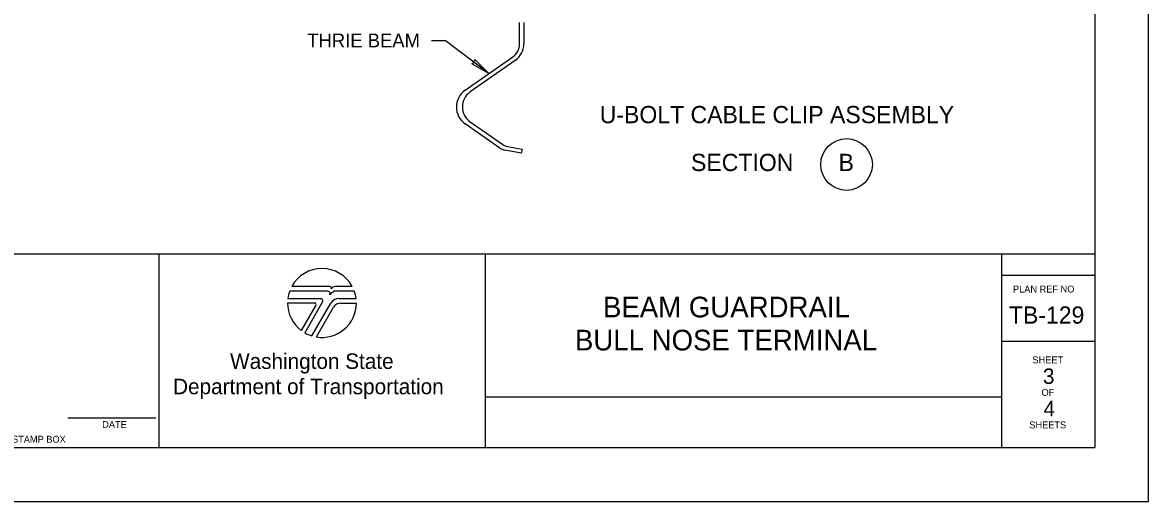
# Model space of a CAD drawing. Extents: x 1312564.2 to 1312581.5, y 1207298.4 to 1207352.6.
# Drawn here: x 1312574.93 to 1312581.48, y 1207327.22 to 1207330 of the extents above; entities that cross this region are included whole.
import ezdxf

# ---------------------------------------------------------------- set-up
doc = ezdxf.new("R2010")
doc.units = 0
for name, color, linetype in [('Level 1', 7, 'Continuous'), ('Level 15', 7, 'Continuous'), ('Level 16', 7, 'Continuous'), ('Level 2', 7, 'Continuous'), ('Level 20', 7, 'Continuous'), ('Level 36', 7, 'Continuous'), ('Level 63', 7, 'Continuous'), ('Level 9', 7, 'Continuous'), ('SH_GI_SheetTextInCells', 7, 'Continuous')]:
    doc.layers.add(name, color=color, linetype=linetype)

msp = doc.modelspace()

# ---------------------------------------------------------------- linework, layer by layer
at = {"layer": 'Level 1'}
for p, q in [((1312581.1655, 1207337.9084), (1312581.1655, 1207327.5334)), ((1312565.4155, 1207328.6593), (1312581.1655, 1207328.6593)), ((1312575.7244, 1207328.6593), (1312575.7244, 1207327.5334)), ((1312577.621, 1207328.6593), (1312577.621, 1207327.5334)), ((1312580.6233, 1207328.6593), (1312580.6233, 1207327.5334)), ((1312580.6233, 1207328.5342), (1312581.1655, 1207328.5342)), ((1312580.6233, 1207328.151), (1312581.1655, 1207328.151)), ((1312577.621, 1207327.8288), (1312580.6233, 1207327.8288)), ((1312575.1952, 1207327.7067), (1312575.7069, 1207327.7067)), ((1312565.4155, 1207327.5334), (1312581.1655, 1207327.5334))]:
    msp.add_line(p, q, dxfattribs=at)
at = {"layer": 'Level 15'}
for p in [(1312577.3093, 1207329.8977), (1312577.6434, 1207329.7054)]:
    msp.add_line(p, (1312577.3894, 1207329.8977), dxfattribs=at)
msp.add_lwpolyline([(1312577.6434, 1207329.7054), (1312577.5433, 1207329.7625), (1312577.5565, 1207329.7712), (1312577.5613, 1207329.7863)], close=True, dxfattribs=at)
at = {"layer": 'Level 16'}
for p, q in [((1312577.8208, 1207329.8782), (1312577.8208, 1207330.0018)), ((1312577.8463, 1207330.0018), (1312577.8463, 1207329.8782)), ((1312577.505, 1207329.6088), (1312577.7818, 1207329.8021)), ((1312577.796, 1207329.7817), (1312577.534, 1207329.5987)), ((1312577.7076, 1207329.2733), (1312577.5045, 1207329.4145)), ((1312577.5342, 1207329.4249), (1312577.7234, 1207329.2934)), ((1312577.752, 1207329.2816), (1312577.8357, 1207329.2669))]:
    msp.add_line(p, q, dxfattribs=at)
msp.add_lwpolyline([(1312577.8357, 1207329.2669), (1312577.8302, 1207329.244), (1312577.7355, 1207329.2617)], dxfattribs=at)
for centre, radius, start, end in [((1312577.7282, 1207329.8776), 0.0925, 305.33624, 0.39712), ((1312577.7286, 1207329.8782), 0.1177, 304.93912, 0), ((1312577.5724, 1207329.5115), 0.1184, 124.71674, 234.96964), ((1312577.5947, 1207329.5119), 0.1059, 124.93912, 235.19201), ((1312577.7645, 1207329.3526), 0.0721, 235.19199, 259.99994), ((1312577.7487, 1207329.3325), 0.0721, 235.19199, 259.41323)]:
    msp.add_arc(centre, radius, start, end, dxfattribs=at)
at = {"layer": 'Level 2'}
msp.add_lwpolyline([(1312564.478, 1207327.2209), (1312581.478, 1207327.2209), (1312581.478, 1207338.2209), (1312564.478, 1207338.2209)], close=True, dxfattribs=at)
at = {"layer": 'Level 63'}
for p, q in [((1312576.7049, 1207328.4427), (1312576.4852, 1207328.4427)), ((1312576.7185, 1207328.4687), (1312576.497, 1207328.4687)), ((1312576.8485, 1207328.4687), (1312576.7506, 1207328.4687)), ((1312576.7585, 1207328.4427), (1312576.7584, 1207328.4427)), ((1312576.8603, 1207328.4427), (1312576.7585, 1207328.4427)), ((1312576.4727, 1207328.3734), (1312576.6303, 1207328.3734)), ((1312576.4745, 1207328.3994), (1312576.6651, 1207328.3994)), ((1312576.6374, 1207328.361), (1312576.5519, 1207328.214)), ((1312576.6765, 1207328.3797), (1312576.5722, 1207328.2006)), ((1312576.6144, 1207328.1821), (1312576.7244, 1207328.3724)), ((1312576.7713, 1207328.3994), (1312576.871, 1207328.3994)), ((1312576.7809, 1207328.3727), (1312576.8727, 1207328.3727)), ((1312576.6399, 1207328.1761), (1312576.7397, 1207328.3489))]:
    msp.add_line(p, q, dxfattribs=at)
for centre, radius, start, end in [((1312576.6727, 1207328.3734), 0.2, 28.47865, 151.53204), ((1312576.6727, 1207328.3734), 0.2, 159.69598, 172.50569), ((1312576.7049, 1207328.428), 0.0148, 327.8418, 89.99855), ((1312576.7584, 1207328.3943), 0.0484, 89.99529, 147.82376), ((1312576.7184, 1207328.4597), 0.00903, 329.87418, 90.00328), ((1312576.7506, 1207328.44), 0.0287, 90.00721, 148.16763), ((1312576.6727, 1207328.3734), 0.2, 7.49431, 20.29406), ((1312576.6727, 1207328.3734), 0.2, 179.99864, 232.84327), ((1312576.6303, 1207328.3651), 0.0082, 329.74356, 90), ((1312576.6727, 1207328.3734), 0.2, 260.54554, 359.80857), ((1312576.6651, 1207328.3863), 0.0131, 329.76834, 90), ((1312576.7713, 1207328.3453), 0.0542, 90, 149.99738), ((1312576.7809, 1207328.3252), 0.0476, 90, 150.05432), ((1312576.6727, 1207328.3734), 0.2, 239.79292, 253.0448)]:
    msp.add_arc(centre, radius, start, end, dxfattribs=at)
at = {"layer": 'Level 9'}
msp.add_circle((1312579.7225, 1207329.1776), 0.1501, dxfattribs=at)

# ---------------------------------------------------------------- texts
at = {"layer": 'Level 1'}
msp.add_text('PLAN REF NO', height=0.040032, dxfattribs=at).set_placement((1312580.6902, 1207328.4341))
at = {"layer": 'Level 20'}
for s, height, p in [('THRIE BEAM', 0.08008, (1312576.5876, 1207329.8576)), ('U-BOLT CABLE CLIP ASSEMBLY', 0.100096, (1312578.2875, 1207329.4173)), ('SECTION', 0.1001, (1312578.8182, 1207329.1394)), ('B', 0.1001, (1312579.6763, 1207329.1394)), ('BEAM GUARDRAIL', 0.12, (1312578.3064, 1207328.2898)), ('BULL NOSE TERMINAL', 0.12, (1312578.1434, 1207328.0978))]:
    msp.add_text(s, height=height, dxfattribs=at).set_placement(p)
at = {"layer": 'Level 36'}
for s, height, p in [('TB-129', 0.1, (1312580.6666, 1207328.2534)), ('3', 0.09, (1312580.8645, 1207327.9032)), ('4', 0.09, (1312580.8679, 1207327.7152))]:
    msp.add_text(s, height=height, dxfattribs=at).set_placement(p)
at = {"layer": 'SH_GI_SheetTextInCells'}
for s, height, p in [('Washington State', 0.090072, (1312576.1384, 1207327.9904)), ('SHEET', 0.04003, (1312580.8032, 1207328.0229)), ('Department of Transportation', 0.090072, (1312575.807, 1207327.8435)), ('OF', 0.04003, (1312580.8561, 1207327.8341)), ('DATE', 0.04003, (1312575.3949, 1207327.6474)), ('SHEETS', 0.04003, (1312580.7853, 1207327.6453)), ('P.E. STAMP BOX', 0.040032, (1312574.7545, 1207327.562))]:
    msp.add_text(s, height=height, dxfattribs=at).set_placement(p)

doc.saveas('drawing.dxf')
